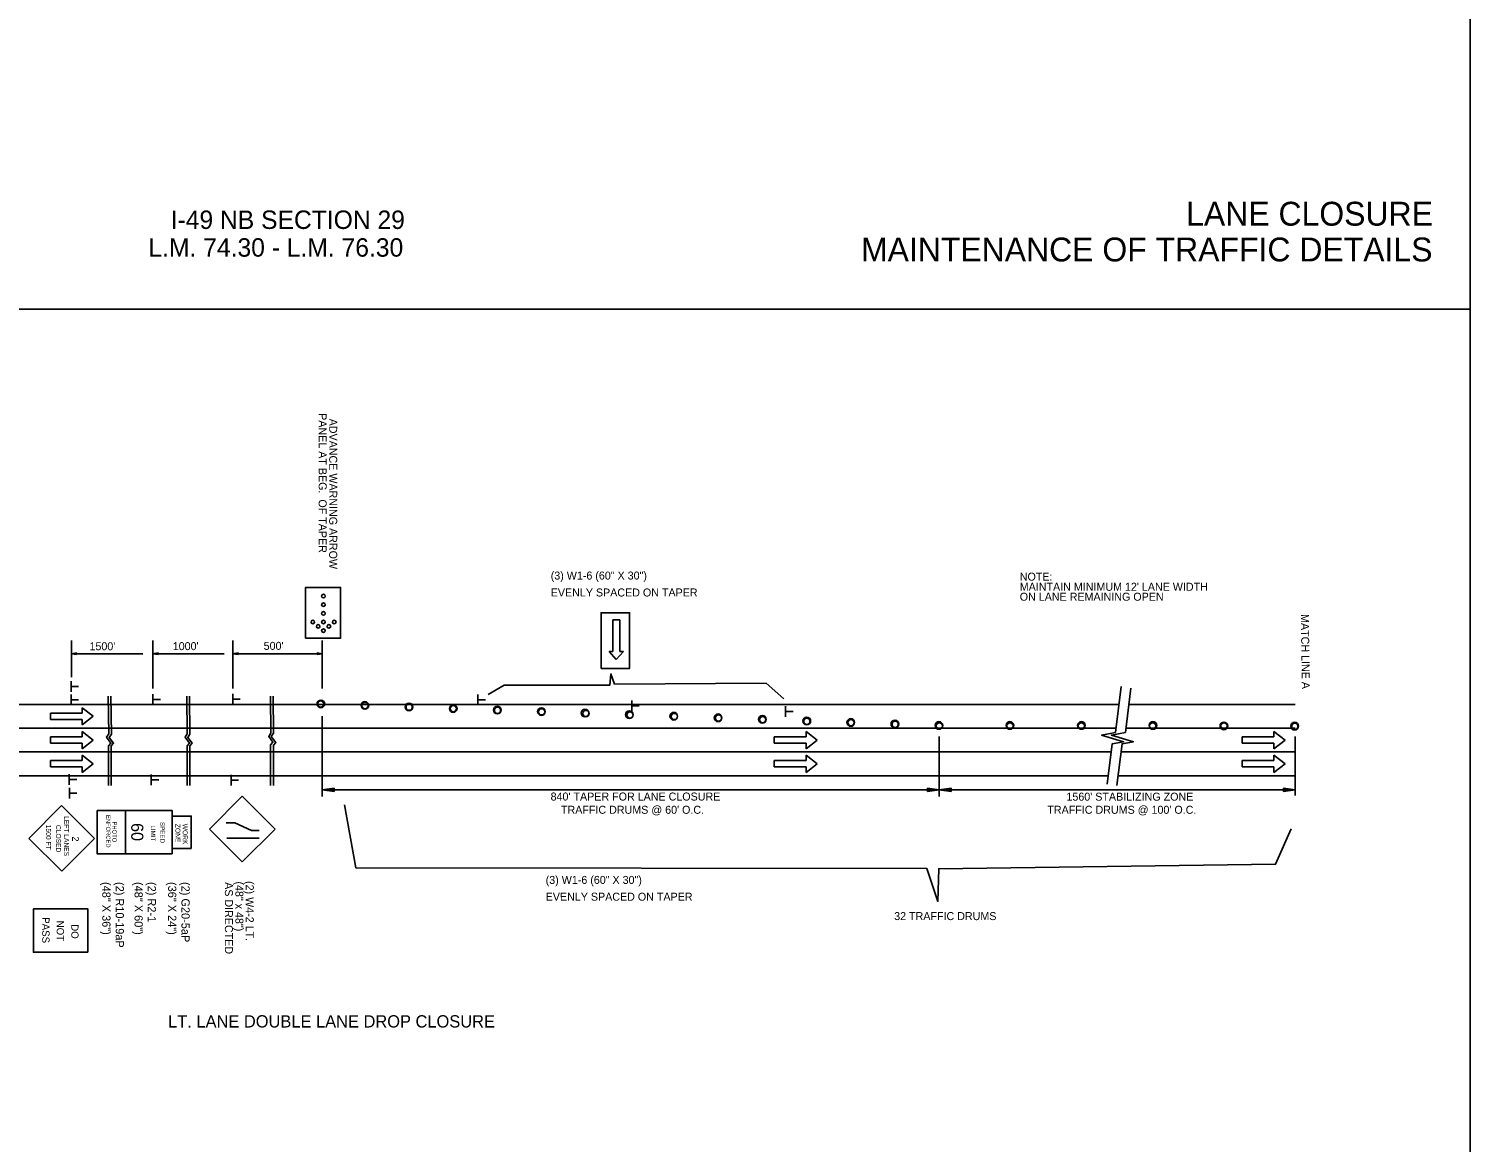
# Model space of a CAD drawing. Extents: x -100 to 745, y -1581 to -107.
# Drawn here: x 239.8 to 345.4, y -651.6 to -570 of the extents above; entities that cross this region are included whole.
import ezdxf

# ---------------------------------------------------------------- set-up
doc = ezdxf.new("R2010")
doc.units = 0
for name, color, linetype in [('Default', 7, 'Continuous'), ('R_Contour Annot', 7, 'Continuous'), ('R_Draft', 7, 'Continuous'), ('R_MOT', 7, 'Continuous'), ('R_ROW', 7, 'Continuous')]:
    doc.layers.add(name, color=color, linetype=linetype)

msp = doc.modelspace()

# ---------------------------------------------------------------- linework, layer by layer
at = {"layer": 'Default'}
for p, q in [((282.59, -613.34), (282.59, -615.67)), ((282.59, -613.34), (283.11, -613.34)), ((283.11, -613.34), (283.11, -615.67)), ((242.94, -614.85), (242.94, -617.53)), ((248.91, -614.85), (248.91, -618.37)), ((254.77, -614.85), (254.77, -618.37)), ((261.31, -614.85), (261.31, -618.37)), ((243.32, -615.77), (242.94, -615.83)), ((242.94, -615.83), (248.16, -615.83)), ((243.32, -615.88), (242.94, -615.83)), ((243.32, -615.78), (243.01, -615.83)), ((243.32, -615.87), (243.01, -615.83)), ((243.32, -615.79), (243.07, -615.83)), ((243.32, -615.87), (243.07, -615.83)), ((243.32, -615.8), (243.13, -615.83)), ((243.32, -615.86), (243.13, -615.83)), ((243.32, -615.81), (243.2, -615.83)), ((243.32, -615.85), (243.2, -615.83)), ((243.32, -615.82), (243.26, -615.83)), ((243.32, -615.84), (243.26, -615.83)), ((243.32, -615.88), (243.32, -615.77)), ((249.29, -615.77), (248.91, -615.83)), ((248.91, -615.83), (254.13, -615.83)), ((249.29, -615.88), (248.91, -615.83)), ((249.29, -615.78), (248.98, -615.83)), ((249.29, -615.87), (248.98, -615.83)), ((249.29, -615.79), (249.04, -615.83)), ((249.29, -615.87), (249.04, -615.83)), ((249.29, -615.8), (249.1, -615.83)), ((249.29, -615.86), (249.1, -615.83)), ((249.29, -615.81), (249.17, -615.83)), ((249.29, -615.85), (249.17, -615.83)), ((249.29, -615.82), (249.23, -615.83)), ((249.29, -615.84), (249.23, -615.83)), ((249.29, -615.88), (249.29, -615.77)), ((255.14, -615.77), (254.77, -615.83)), ((254.77, -615.83), (261.31, -615.83)), ((255.14, -615.88), (254.77, -615.83)), ((255.14, -615.78), (254.83, -615.83)), ((255.14, -615.87), (254.83, -615.83)), ((255.14, -615.79), (254.89, -615.83)), ((255.14, -615.87), (254.89, -615.83)), ((255.14, -615.8), (254.95, -615.83)), ((255.14, -615.86), (254.95, -615.83)), ((255.14, -615.81), (255.02, -615.83)), ((255.14, -615.85), (255.02, -615.83)), ((255.14, -615.82), (255.08, -615.83)), ((255.14, -615.84), (255.08, -615.83)), ((255.14, -615.88), (255.14, -615.77)), ((260.94, -615.77), (261.31, -615.83)), ((260.94, -615.77), (260.94, -615.88)), ((260.94, -615.78), (261.25, -615.83)), ((260.94, -615.79), (261.19, -615.83)), ((260.94, -615.8), (261.12, -615.83)), ((260.94, -615.81), (261.06, -615.83)), ((260.94, -615.82), (261, -615.83)), ((260.94, -615.88), (261.31, -615.83)), ((260.94, -615.85), (261.06, -615.83)), ((260.94, -615.87), (261.19, -615.83)), ((260.94, -615.87), (261.25, -615.83)), ((260.94, -615.86), (261.12, -615.83)), ((260.94, -615.84), (261, -615.83)), ((282.59, -615.67), (282.33, -615.67)), ((282.33, -615.67), (282.85, -616.24)), ((282.85, -616.24), (283.37, -615.67)), ((283.11, -615.67), (283.37, -615.67)), ((242.91, -618.62), (242.91, -617.84)), ((242.92, -618.23), (243.45, -618.23)), ((236.66, -619.54), (245.32, -619.54)), ((242.91, -619.59), (242.91, -618.8)), ((242.92, -619.2), (243.45, -619.2)), ((243.72, -619.78), (243.72, -620.17)), ((243.72, -619.78), (244.54, -620.41)), ((245.32, -619.54), (261.31, -619.54)), ((248.91, -619.56), (248.91, -618.78)), ((248.93, -619.18), (249.46, -619.18)), ((254.77, -619.54), (254.77, -618.76)), ((254.78, -619.15), (255.31, -619.15)), ((261.31, -619.54), (319.67, -619.54)), ((272.72, -618.82), (272.72, -619.6)), ((272.73, -619.21), (273.26, -619.21)), ((283.99, -619.24), (283.99, -620.03)), ((284, -619.63), (284.53, -619.63)), ((295.26, -619.67), (295.26, -620.45)), ((320.4, -619.54), (332.59, -619.54)), ((243.72, -620.17), (241.4, -620.17)), ((241.4, -620.17), (241.4, -620.65)), ((243.72, -620.65), (241.4, -620.65)), ((244.54, -620.41), (243.72, -621.04)), ((243.72, -620.65), (243.72, -621.04)), ((261.31, -620.39), (261.31, -626.29)), ((295.27, -620.06), (295.8, -620.06)), ((236.66, -621.28), (245.32, -621.28)), ((243.72, -621.91), (241.4, -621.91)), ((241.4, -621.91), (241.4, -622.38)), ((243.72, -621.52), (243.72, -621.91)), ((243.72, -621.52), (244.54, -622.15)), ((245.32, -621.28), (261.31, -621.28)), ((261.31, -621.28), (319.46, -621.28)), ((296.76, -621.91), (294.43, -621.91)), ((294.43, -622.38), (294.43, -621.91)), ((296.76, -621.91), (296.76, -621.52)), ((297.58, -622.15), (296.76, -621.52)), ((306.51, -626.29), (306.51, -621.9)), ((320.19, -621.28), (332.59, -621.28)), ((331.03, -621.91), (328.7, -621.91)), ((328.7, -622.38), (328.7, -621.91)), ((331.03, -621.91), (331.03, -621.52)), ((331.85, -622.15), (331.03, -621.52)), ((332.59, -626.21), (332.59, -621.9)), ((243.72, -622.38), (241.4, -622.38)), ((244.54, -622.15), (243.72, -622.78)), ((243.72, -622.38), (243.72, -622.78)), ((296.76, -622.38), (294.43, -622.38)), ((296.76, -622.78), (297.58, -622.15)), ((296.76, -622.78), (296.76, -622.38)), ((331.03, -622.38), (328.7, -622.38)), ((331.03, -622.78), (331.85, -622.15)), ((331.03, -622.78), (331.03, -622.38)), ((236.66, -623.02), (245.32, -623.02)), ((243.72, -623.65), (241.4, -623.65)), ((241.4, -623.65), (241.4, -624.12)), ((243.72, -623.25), (243.72, -623.65)), ((243.72, -623.25), (244.54, -623.89)), ((244.54, -623.89), (243.72, -624.52)), ((245.32, -623.02), (261.31, -623.02)), ((261.31, -623.02), (319.1, -623.02)), ((296.76, -623.65), (294.43, -623.65)), ((294.43, -624.12), (294.43, -623.65)), ((296.76, -623.65), (296.76, -623.25)), ((297.58, -623.89), (296.76, -623.25)), ((296.76, -624.52), (297.58, -623.89)), ((319.83, -623.02), (332.59, -623.02)), ((331.03, -623.65), (328.7, -623.65)), ((328.7, -624.12), (328.7, -623.65)), ((331.03, -623.65), (331.03, -623.25)), ((331.85, -623.89), (331.03, -623.25)), ((331.03, -624.52), (331.85, -623.89)), ((236.66, -624.76), (246.24, -624.76)), ((243.72, -624.12), (241.4, -624.12)), ((242.78, -625.43), (242.78, -624.65)), ((242.79, -625.04), (243.33, -625.04)), ((243.72, -624.12), (243.72, -624.52)), ((245.32, -624.76), (261.31, -624.76)), ((248.79, -625.45), (248.79, -624.67)), ((248.8, -625.06), (249.33, -625.06)), ((254.64, -625.47), (254.64, -624.69)), ((254.65, -625.08), (255.18, -625.08)), ((261.31, -624.76), (318.89, -624.76)), ((296.76, -624.12), (294.43, -624.12)), ((296.76, -624.52), (296.76, -624.12)), ((319.62, -624.76), (332.59, -624.76)), ((331.03, -624.12), (328.7, -624.12)), ((331.03, -624.52), (331.03, -624.12)), ((242.79, -626.44), (242.79, -625.65)), ((242.8, -626.05), (243.33, -626.05)), ((262.18, -625.67), (261.31, -625.8)), ((306.51, -625.8), (261.31, -625.8)), ((261.31, -625.8), (262.18, -625.93)), ((262.18, -625.93), (262.18, -625.67)), ((306.51, -625.8), (305.64, -625.67)), ((305.64, -625.67), (305.64, -625.93)), ((305.64, -625.93), (306.51, -625.8)), ((307.38, -625.67), (306.51, -625.8)), ((332.59, -625.8), (306.51, -625.8)), ((306.51, -625.8), (307.38, -625.93)), ((307.38, -625.93), (307.38, -625.67)), ((332.59, -625.8), (331.72, -625.67)), ((331.72, -625.67), (331.72, -625.93)), ((331.72, -625.93), (332.59, -625.8)), ((239.82, -629.36), (242.22, -626.95)), ((244.63, -629.35), (242.22, -626.95)), ((255.45, -626.26), (253.04, -628.67)), ((255.45, -626.26), (257.86, -628.67)), ((254.28, -628.21), (254.9, -628.21)), ((254.9, -628.21), (256.12, -628.77)), ((253.04, -628.67), (255.45, -631.08)), ((257.86, -628.67), (255.45, -631.08)), ((256.12, -628.77), (256.7, -628.77)), ((242.23, -631.76), (239.82, -629.36)), ((242.23, -631.76), (244.63, -629.35)), ((254.33, -629.33), (256.7, -629.33))]:
    msp.add_line(p, q, dxfattribs=at)
for points in [[(260.09, -614.69), (260.09, -610.97), (262.66, -610.97), (262.66, -614.69)], [(281.74, -616.9), (281.74, -612.82), (283.83, -612.82), (283.83, -616.9)], [(246.91, -630.49), (244.83, -630.49), (244.83, -627.32), (246.91, -627.32)], [(250.32, -630.49), (246.91, -630.49), (246.91, -627.32), (250.32, -627.32)], [(251.71, -630.1), (250.32, -630.1), (250.32, -627.72), (251.71, -627.72)], [(244.15, -637.7), (240.15, -637.7), (240.15, -634.52), (244.15, -634.52)]]:
    msp.add_lwpolyline(points, close=True, dxfattribs=at)
for points in [[(273.47, -618.8), (274.63, -618.12), (282.39, -618.12), (282.46, -617.3), (282.73, -618.05), (293.83, -617.98), (295.13, -619.14)], [(318.81, -625.39), (319.18, -622.42), (320.01, -622.27), (318.4, -621.79), (319.42, -621.59), (319.83, -618.23)], [(319.53, -625.47), (319.91, -622.42), (320.73, -622.27), (319.13, -621.79), (320.15, -621.59), (320.54, -618.35)], [(245.63, -618.93), (245.68, -621.7), (245.51, -621.94), (245.83, -622.38), (245.66, -622.58), (245.66, -625.47)], [(245.83, -618.93), (245.88, -621.71), (245.71, -621.95), (246.03, -622.38), (245.86, -622.58), (245.86, -625.47)], [(251.38, -618.93), (251.42, -621.7), (251.26, -621.94), (251.58, -622.38), (251.41, -622.58), (251.41, -625.47)], [(251.58, -618.93), (251.62, -621.71), (251.46, -621.95), (251.78, -622.38), (251.61, -622.58), (251.61, -625.47)], [(257.51, -618.93), (257.55, -621.64), (257.39, -621.88), (257.7, -622.31), (257.53, -622.51), (257.53, -625.47)], [(257.71, -618.93), (257.75, -621.65), (257.58, -621.89), (257.9, -622.32), (257.73, -622.52), (257.73, -625.47)], [(262.94, -626.89), (263.77, -631.5), (305.6, -631.55), (306.41, -633.97), (306.48, -631.58), (331.15, -631.25), (332.29, -628.65)]]:
    msp.add_lwpolyline(points, dxfattribs=at)
for centre, radius in [((261.4, -611.6), 0.131), ((261.4, -612.23), 0.131), ((260.62, -613.5), 0.131), ((261.4, -612.87), 0.131), ((261.4, -613.5), 0.131), ((262.19, -613.5), 0.131), ((261.01, -613.82), 0.131), ((261.4, -614.13), 0.131), ((261.8, -613.82), 0.131), ((261.21, -619.5), 0.281), ((261.19, -619.51), 0.229), ((261.21, -619.51), 0.229), ((264.44, -619.61), 0.281), ((264.44, -619.62), 0.229), ((267.67, -619.72), 0.281), ((267.68, -619.74), 0.229), ((270.91, -619.84), 0.281), ((270.92, -619.85), 0.229), ((274.14, -619.95), 0.281), ((274.15, -619.97), 0.229), ((277.37, -620.06), 0.281), ((277.39, -620.08), 0.229), ((280.56, -620.17), 0.281), ((280.63, -620.2), 0.229), ((283.81, -620.28), 0.281), ((283.86, -620.31), 0.229), ((287.06, -620.4), 0.281), ((287.1, -620.42), 0.229), ((290.31, -620.52), 0.281), ((290.34, -620.54), 0.229), ((293.56, -620.63), 0.281), ((293.57, -620.65), 0.229), ((296.81, -620.75), 0.281), ((296.81, -620.77), 0.229), ((300.03, -620.86), 0.281), ((300.05, -620.88), 0.229), ((303.26, -620.97), 0.281), ((303.28, -621), 0.229), ((306.49, -621.08), 0.281), ((311.69, -621.08), 0.281), ((316.93, -621.08), 0.281), ((322.17, -621.08), 0.281), ((327.36, -621.11), 0.281), ((332.55, -621.13), 0.281), ((306.51, -621.11), 0.229), ((306.52, -621.11), 0.229), ((311.7, -621.11), 0.229), ((316.92, -621.11), 0.229), ((322.15, -621.11), 0.229), ((327.38, -621.11), 0.229), ((332.56, -621.14), 0.229)]:
    msp.add_circle(centre, radius, dxfattribs=at)
at = {"layer": 'R_Contour Annot'}
for points in [[(175.41, -480.58), (345.41, -480.58), (345.41, -590.58), (175.41, -590.58)], [(175.41, -590.58), (345.41, -590.58), (345.41, -700.58), (175.41, -700.58)]]:
    msp.add_lwpolyline(points, close=True, dxfattribs=at)
at = {"layer": 'R_Draft'}
for points in [[(175.41, -480.58), (175.41, -590.58), (345.41, -590.58), (345.41, -480.58)], [(175.41, -590.58), (175.41, -700.58), (345.41, -700.58), (345.41, -590.58)]]:
    msp.add_lwpolyline(points, close=True, dxfattribs=at)

# ---------------------------------------------------------------- texts
at = {"layer": 'Default'}
for s, height, p in [('I-49 NB SECTION 29', 1.35, (250.21, -584.7)), ('L.M. 74.30 - L.M. 76.30', 1.35, (248.58, -586.73)), ('NOTE:', 0.586, (312.41, -610.47)), ('ON LANE REMAINING OPEN', 0.5862, (312.41, -611.94)), ("MAINTAIN MINIMUM 12' LANE WIDTH", 0.5862, (312.41, -611.21)), ("1500'", 0.586, (244.26, -615.57)), ("1000'", 0.586, (250.36, -615.56)), ("500'", 0.586, (257.02, -615.54)), ("840' TAPER FOR LANE CLOSURE", 0.5862, (278.04, -626.58)), ("1560' STABILIZING ZONE", 0.5862, (315.83, -626.59)), ("TRAFFIC DRUMS @ 60' O.C.", 0.5862, (278.8, -627.55)), ("TRAFFIC DRUMS @ 100' O.C.", 0.5862, (314.43, -627.55)), ('32 TRAFFIC DRUMS', 0.5862, (303.21, -635.34))]:
    msp.add_text(s, height=height, dxfattribs=at).set_placement(p)
for s, height, rotation, p in [('PANEL AT BEG.  OF TAPER', 0.5862, 270, (261.05, -598.2)), ('ADVANCE WARNING ARROW', 0.5862, 270, (261.82, -598.6)), ('(3) W1-6 (60" X 30")', 0.5862, 0.0075, (278.05, -610.39)), ('EVENLY SPACED ON TAPER', 0.5862, 0.0075, (278.05, -611.63)), ('MATCH LINE A', 0.5862, 270.8059, (333, -612.92)), ('LEFT LANES', 0.354, 270.1004, (242.4, -627.72)), ('ENFORCED', 0.308, 270.0872, (245.48, -627.64)), ('PHOTO', 0.308, 270.0872, (245.94, -628.12)), ('SPEED', 0.33, 270, (249.44, -628.15)), ('1500 FT', 0.357, 270.0006, (241.08, -628.35)), ('CLOSED', 0.354, 270.1003, (241.81, -628.37)), ('2', 0.5, 270, (242.99, -629.21)), ('60', 0.885, 270, (247.32, -628.23)), ('LIMIT', 0.33, 270, (248.76, -628.4)), ('ZONE', 0.354, 270.1004, (250.56, -628.29)), ('WORK', 0.354, 270.1004, (251.09, -628.28)), ('(3) W1-6 (60" X 30")', 0.5862, 0.0075, (277.68, -632.69)), ('(48" X 36")', 0.6, 270, (245.2, -632.55)), ('(2) R10-19aP', 0.6, 270, (246.18, -632.55)), ('(48" X 60")', 0.6, 270, (247.56, -632.55)), ('(2) R2-1', 0.6, 270, (248.53, -632.55)), ('(36" X 24")', 0.6, 270, (250.02, -632.55)), ('(2) G20-5aP', 0.6, 270, (251, -632.55)), ('AS DIRECTED', 0.5862, 270, (254.18, -632.56)), ('(48" x 48")', 0.5862, 270, (254.95, -632.51)), ('(2) W4-2 LT.', 0.5862, 270, (255.71, -632.48)), ('EVENLY SPACED ON TAPER', 0.5862, 0.0075, (277.68, -633.92)), ('PASS', 0.532, 270, (240.8, -635.13)), ('NOT', 0.532, 270, (241.86, -635.38)), ('DO', 0.532, 270, (242.93, -635.64))]:
    msp.add_text(s, height=height, rotation=rotation, dxfattribs=at).set_placement(p)
at = {"layer": 'R_MOT'}
for s, p in [('LANE CLOSURE', (324.6, -584.46)), ('MAINTENANCE OF TRAFFIC DETAILS', (300.78, -587.08))]:
    msp.add_text(s, height=1.75, dxfattribs=at).set_placement(p)
at = {"layer": 'R_ROW'}
msp.add_text('LT. LANE DOUBLE LANE DROP CLOSURE', height=0.9, dxfattribs=at).set_placement((250.02, -643.21))

doc.saveas('drawing.dxf')
